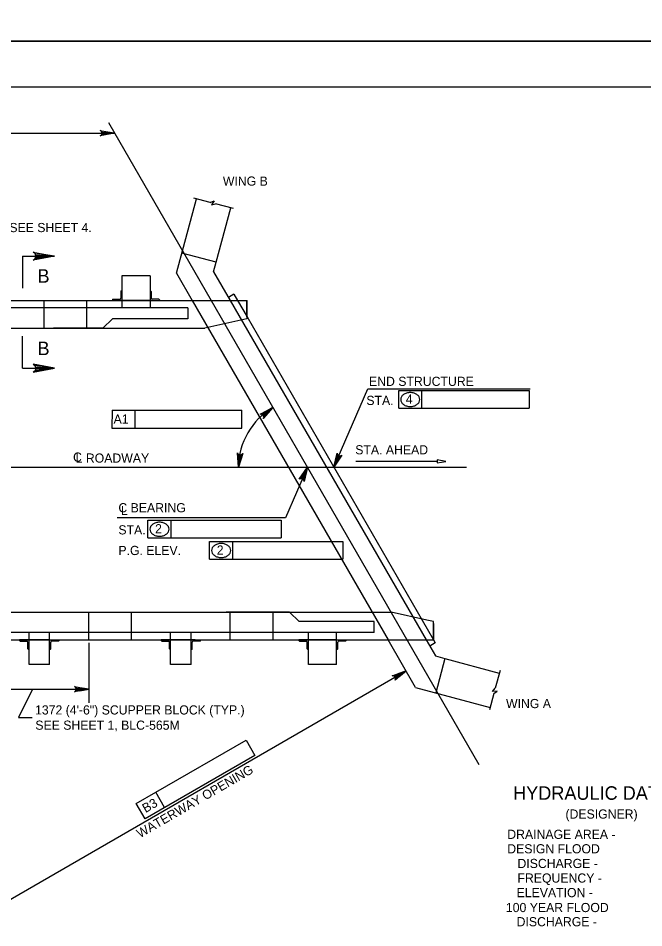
# Model space of a CAD drawing. Extents: x 638263 to 640360, y 293683 to 298655.
# Drawn here: x 638685.2 to 638890, y 296957.1 to 297255 of the extents above; entities that cross this region are included whole.
import ezdxf

# ---------------------------------------------------------------- set-up
doc = ezdxf.new("R2010")
doc.units = 0
for name, color, linetype in [('2', 7, 'Continuous'), ('3', 7, 'Continuous'), ('4', 7, 'Continuous'), ('PLT-BNDY', 7, 'Continuous')]:
    doc.layers.add(name, color=color, linetype=linetype)

msp = doc.modelspace()

# ---------------------------------------------------------------- linework, layer by layer
at = {"layer": '2'}
for p, q in [((638475.46, 297232.46), (639261.46, 297232.46)), ((638736.95, 297171.46), (638743.49, 297195.86)), ((638749.97, 297175.06), (638754.74, 297192.85)), ((638686.53, 297177.06), (638686.53, 297166.58)), ((638686.53, 297177.06), (638697.02, 297177.06)), ((638749.97, 297175.06), (638738.72, 297178.07)), ((638749.12, 297171.91), (638749.97, 297175.06)), ((638728.33, 297170.65), (638719.09, 297170.65)), ((638719.09, 297170.65), (638719.09, 297160.17)), ((638728.33, 297170.65), (638728.33, 297160.17)), ((638736.95, 297171.46), (638742.09, 297162.56)), ((638749.12, 297171.91), (638754.52, 297162.56)), ((638718.73, 297165.47), (638718.73, 297163.29)), ((638718.91, 297165.65), (638719.09, 297165.65)), ((638719.09, 297165.65), (638719.09, 297162.56)), ((638728.51, 297165.65), (638728.33, 297165.65)), ((638728.33, 297165.65), (638728.33, 297162.56)), ((638728.69, 297165.47), (638728.69, 297163.29)), ((638755.81, 297164.58), (638753.97, 297163.51)), ((638755.81, 297164.58), (638756.98, 297162.56)), ((638548.21, 297162.56), (638760.09, 297162.56)), ((638612.98, 297162.56), (638760.07, 297162.56)), ((638693.52, 297162.56), (638693.52, 297153.44)), ((638707.54, 297162.56), (638707.54, 297153.44)), ((638716, 297162.74), (638716, 297162.56)), ((638719.09, 297162.56), (638716, 297162.56)), ((638716.18, 297162.92), (638718.36, 297162.92)), ((638728.33, 297162.56), (638719.09, 297162.56)), ((638728.33, 297162.56), (638731.42, 297162.56)), ((638731.24, 297162.92), (638729.06, 297162.92)), ((638731.42, 297162.74), (638731.42, 297162.56)), ((638742.09, 297162.56), (638806.28, 297051.39)), ((638754.52, 297162.56), (638818.71, 297051.39)), ((638756.98, 297162.56), (638760.09, 297157.17)), ((638760.07, 297157.18), (638760.07, 297162.56)), ((638760.07, 297162.56), (638760.07, 297156.53)), ((638760.09, 297157.18), (638760.09, 297162.56)), ((638740.65, 297160.17), (638612.81, 297160.17)), ((638740.65, 297160.17), (638740.65, 297156.53)), ((638712.92, 297153.44), (638716.01, 297156.53)), ((638740.65, 297156.53), (638716.01, 297156.53)), ((638760.07, 297156.53), (638746.22, 297153.44)), ((638760.09, 297157.17), (638817.43, 297057.86)), ((638595.36, 297153.44), (638746.22, 297153.44)), ((638712.92, 297153.44), (638696.76, 297153.44)), ((638686.53, 297140.33), (638686.53, 297150.82)), ((638686.53, 297140.33), (638697.02, 297140.33)), ((638656.45, 297060.51), (638807.31, 297060.51)), ((638708.24, 297051.39), (638708.24, 297060.51)), ((638722.27, 297051.39), (638722.27, 297060.51)), ((638774.01, 297060.51), (638753.23, 297060.51)), ((638754.61, 297051.39), (638754.61, 297060.51)), ((638768.63, 297051.39), (638768.63, 297060.51)), ((638774.01, 297060.51), (638777.1, 297057.42)), ((638818.99, 297057.9), (638807.31, 297060.51)), ((638801.74, 297057.42), (638777.1, 297057.42)), ((638801.74, 297053.78), (638801.74, 297057.42)), ((638817.43, 297057.86), (638821.16, 297051.39)), ((638821.16, 297057.42), (638818.99, 297057.9)), ((638821.16, 297051.39), (638821.16, 297057.42)), ((638821.16, 297056.77), (638821.16, 297051.39)), ((638801.74, 297053.78), (638673.9, 297053.78)), ((638688.71, 297043.3), (638688.71, 297053.78)), ((638695.44, 297043.3), (638695.44, 297053.78)), ((638735.07, 297043.3), (638735.07, 297053.78)), ((638741.8, 297043.3), (638741.8, 297053.78)), ((638780.18, 297043.3), (638780.18, 297053.78)), ((638789.42, 297043.3), (638789.42, 297053.78)), ((638674.07, 297051.39), (638821.16, 297051.39)), ((638685.62, 297051.21), (638685.62, 297051.39)), ((638688.71, 297051.39), (638685.62, 297051.39)), ((638685.8, 297051.02), (638687.98, 297051.02)), ((638688.35, 297048.48), (638688.35, 297050.66)), ((638695.44, 297051.39), (638688.71, 297051.39)), ((638688.71, 297048.3), (638688.71, 297051.39)), ((638695.44, 297048.3), (638695.44, 297051.39)), ((638695.44, 297051.39), (638698.53, 297051.39)), ((638695.8, 297048.48), (638695.8, 297050.66)), ((638698.35, 297051.02), (638696.16, 297051.02)), ((638698.53, 297051.21), (638698.53, 297051.39)), ((638731.98, 297051.21), (638731.98, 297051.39)), ((638735.07, 297051.39), (638731.98, 297051.39)), ((638732.16, 297051.02), (638734.35, 297051.02)), ((638743.05, 297051.39), (638733.82, 297051.39)), ((638734.71, 297048.48), (638734.71, 297050.66)), ((638741.8, 297051.39), (638735.07, 297051.39)), ((638735.07, 297048.3), (638735.07, 297051.39)), ((638741.8, 297048.3), (638741.8, 297051.39)), ((638741.8, 297051.39), (638744.89, 297051.39)), ((638742.16, 297048.48), (638742.16, 297050.66)), ((638744.71, 297051.02), (638742.53, 297051.02)), ((638744.89, 297051.21), (638744.89, 297051.39)), ((638777.09, 297051.21), (638777.09, 297051.39)), ((638780.18, 297051.39), (638777.09, 297051.39)), ((638777.27, 297051.02), (638779.45, 297051.02)), ((638779.82, 297048.48), (638779.82, 297050.66)), ((638789.42, 297051.39), (638780.18, 297051.39)), ((638780.18, 297048.3), (638780.18, 297051.39)), ((638789.42, 297048.3), (638789.42, 297051.39)), ((638789.42, 297051.39), (638792.51, 297051.39)), ((638789.78, 297048.48), (638789.78, 297050.66)), ((638792.33, 297051.02), (638790.15, 297051.02)), ((638792.51, 297051.21), (638792.51, 297051.39)), ((638815.27, 297035.81), (638806.28, 297051.39)), ((638818.71, 297051.39), (638821.74, 297046.13)), ((638821.72, 297050.43), (638819.88, 297049.36)), ((638821.16, 297051.39), (638821.72, 297050.43)), ((638688.53, 297048.3), (638688.71, 297048.3)), ((638695.62, 297048.3), (638695.44, 297048.3)), ((638734.89, 297048.3), (638735.07, 297048.3)), ((638741.98, 297048.3), (638741.8, 297048.3)), ((638780, 297048.3), (638780.18, 297048.3)), ((638789.6, 297048.3), (638789.42, 297048.3)), ((638821.74, 297046.13), (638824.89, 297045.29)), ((638824.89, 297045.29), (638821.88, 297034.04)), ((638824.89, 297045.29), (638842.68, 297040.52)), ((638695.44, 297043.3), (638688.71, 297043.3)), ((638741.8, 297043.3), (638735.07, 297043.3)), ((638741.8, 297043.3), (638735.07, 297043.3)), ((638789.42, 297043.3), (638780.18, 297043.3)), ((638815.27, 297035.81), (638839.67, 297029.27))]:
    msp.add_line(p, q, dxfattribs=at)
for points in [[(638697.02, 297177.06), (638690.03, 297175.75), (638690.57, 297176.12), (638690.84, 297176.59), (638690.93, 297177.06), (638690.84, 297177.53), (638690.57, 297178), (638690.03, 297178.37), (638697.02, 297177.06), (638690.57, 297178), (638690.84, 297177.53), (638697.02, 297177.06), (638690.93, 297177.06), (638690.84, 297176.59), (638697.02, 297177.06), (638690.57, 297176.12)], [(638697.02, 297140.33), (638690.03, 297141.64), (638690.57, 297141.27), (638690.84, 297140.8), (638690.93, 297140.33), (638690.84, 297139.86), (638690.57, 297139.39), (638690.03, 297139.02), (638697.02, 297140.33), (638690.57, 297139.39), (638690.84, 297139.86), (638697.02, 297140.33), (638690.93, 297140.33), (638690.84, 297140.8), (638697.02, 297140.33), (638690.57, 297141.27)]]:
    msp.add_lwpolyline(points, dxfattribs=at)
for centre, radius, start, end in [((638718.91, 297165.47), 0.182, 90, 179.9984), ((638728.51, 297165.47), 0.182, 0.0016, 90), ((638716.18, 297162.74), 0.182, 90, 179.9984), ((638718.36, 297163.29), 0.364, 270, 359.9984), ((638729.06, 297163.29), 0.364, 180.0016, 270), ((638731.24, 297162.74), 0.182, 0.0016, 90), ((638685.8, 297051.21), 0.182, 180.0016, 270), ((638687.98, 297050.66), 0.364, 0.0016, 90), ((638696.16, 297050.66), 0.364, 90, 179.9984), ((638698.35, 297051.21), 0.182, 270, 359.9984), ((638732.16, 297051.21), 0.182, 180.0016, 270), ((638734.35, 297050.66), 0.364, 0.0016, 90), ((638742.53, 297050.66), 0.364, 90, 179.9984), ((638744.71, 297051.21), 0.182, 270, 359.9984), ((638777.27, 297051.21), 0.182, 180.0016, 270), ((638779.45, 297050.66), 0.364, 0.0016, 90), ((638790.15, 297050.66), 0.364, 90, 179.9984), ((638792.33, 297051.21), 0.182, 270, 359.9984), ((638688.53, 297048.48), 0.182, 180.0016, 270), ((638695.62, 297048.48), 0.182, 270, 359.9984), ((638734.89, 297048.48), 0.182, 180.0016, 270), ((638741.98, 297048.48), 0.182, 270, 359.9984), ((638780, 297048.48), 0.182, 180.0016, 270), ((638789.6, 297048.48), 0.182, 270, 359.9984)]:
    msp.add_arc(centre, radius, start, end, dxfattribs=at)
at = {"layer": '3'}
for p, q in [((638714.68, 297220.81), (638836.02, 297010.64)), ((638525.28, 297217.32), (638716.69, 297217.32)), ((638748.04, 297194.65), (638742.7, 297196.08)), ((638748.04, 297194.65), (638749.29, 297195.18)), ((638749.29, 297195.18), (638748.43, 297193.88)), ((638748.43, 297193.88), (638749.77, 297194.18)), ((638755.6, 297192.62), (638749.77, 297194.18)), ((638842.92, 297041.39), (638841.35, 297035.55)), ((638840.43, 297034.54), (638841.35, 297035.55)), ((638840.89, 297033.82), (638839.46, 297028.48)), ((638841.98, 297034.64), (638840.43, 297034.54)), ((638840.89, 297033.82), (638841.98, 297034.64))]:
    msp.add_line(p, q, dxfattribs=at)
at = {"layer": '4'}
for p, q in [((638788.52, 297107.93), (638799.64, 297133.65)), ((638799.64, 297133.65), (638852.83, 297133.65)), ((638809.74, 297133.03), (638817.32, 297133.03)), ((638809.74, 297127.26), (638809.74, 297133.03)), ((638817.32, 297127.26), (638817.32, 297133.03)), ((638817.32, 297133.03), (638852.5, 297133.03)), ((638852.5, 297133.03), (638852.5, 297127.26)), ((638715.88, 297126.66), (638715.87, 297120.75)), ((638715.88, 297126.66), (638723.44, 297126.66)), ((638723.43, 297120.75), (638723.44, 297126.66)), ((638723.44, 297126.66), (638758.4, 297126.66)), ((638758.39, 297120.75), (638758.4, 297126.66)), ((638809.74, 297127.26), (638852.5, 297127.26)), ((638715.87, 297120.75), (638758.39, 297120.75)), ((638546.93, 297107.93), (638831.95, 297107.93)), ((638779.85, 297107.93), (638772.67, 297091.32)), ((638822.3, 297109.86), (638795.66, 297109.86)), ((638772.67, 297091.32), (638717.6, 297091.32)), ((638727.65, 297090.56), (638735.22, 297090.56)), ((638727.65, 297084.79), (638727.65, 297090.56)), ((638735.22, 297084.79), (638735.22, 297090.56)), ((638735.22, 297090.56), (638771.23, 297090.56)), ((638771.23, 297090.56), (638771.23, 297084.79)), ((638727.65, 297084.79), (638771.23, 297084.79)), ((638747.84, 297077.82), (638747.84, 297083.59)), ((638747.84, 297083.59), (638755.41, 297083.59)), ((638755.41, 297077.82), (638755.41, 297083.59)), ((638755.41, 297083.59), (638791.42, 297083.59)), ((638791.42, 297083.59), (638791.42, 297077.82)), ((638747.84, 297077.82), (638791.42, 297077.82)), ((638708.24, 297050.46), (638708.24, 297030.82)), ((638677.89, 296963.76), (638812.12, 297041.26)), ((638675.9, 297035.25), (638708.24, 297035.25)), ((638689.86, 297035.25), (638685.27, 297026.02)), ((638685.27, 297026.02), (638689.7, 297026.02)), ((638730.22, 297001.51), (638759.8, 297018.55)), ((638759.8, 297018.55), (638762.67, 297013.56)), ((638762.67, 297013.56), (638726.69, 296992.83)), ((638723.81, 296997.83), (638730.22, 297001.51)), ((638733.1, 296996.52), (638730.22, 297001.51)), ((638726.69, 296992.83), (638723.81, 296997.83))]:
    msp.add_line(p, q, dxfattribs=at)
for points in [[(638716.69, 297217.32), (638712.03, 297216.45), (638712.39, 297216.69), (638712.57, 297217.01), (638712.63, 297217.32), (638712.57, 297217.63), (638712.39, 297217.94), (638712.03, 297218.19), (638716.69, 297217.32), (638712.39, 297217.94), (638712.57, 297217.63), (638716.69, 297217.32), (638712.63, 297217.32), (638712.57, 297217.01), (638716.69, 297217.32), (638712.39, 297216.69)], [(638768.58, 297127.44), (638765.41, 297123.92), (638765.54, 297124.34), (638765.5, 297124.7), (638765.35, 297124.98), (638765.12, 297125.19), (638764.78, 297125.33), (638764.35, 297125.31), (638768.58, 297127.44), (638764.78, 297125.33), (638765.12, 297125.19), (638768.58, 297127.44), (638765.35, 297124.98), (638765.5, 297124.7), (638768.58, 297127.44), (638765.54, 297124.34)], [(638757.31, 297107.91), (638757.01, 297112.64), (638757.22, 297112.26), (638757.5, 297112.04), (638757.81, 297111.94), (638758.12, 297111.96), (638758.46, 297112.11), (638758.75, 297112.43), (638757.31, 297107.91), (638758.46, 297112.11), (638758.12, 297111.96), (638757.31, 297107.91), (638757.81, 297111.94), (638757.5, 297112.04), (638757.31, 297107.91), (638757.22, 297112.26)], [(638788.52, 297107.93), (638789.57, 297112.55), (638789.65, 297112.12), (638789.87, 297111.83), (638790.13, 297111.66), (638790.44, 297111.58), (638790.8, 297111.63), (638791.17, 297111.86), (638788.52, 297107.93), (638790.8, 297111.63), (638790.44, 297111.58), (638788.52, 297107.93), (638790.13, 297111.66), (638789.87, 297111.83), (638788.52, 297107.93), (638789.65, 297112.12)], [(638779.85, 297107.93), (638778.8, 297103.3), (638778.71, 297103.73), (638778.5, 297104.02), (638778.24, 297104.2), (638777.93, 297104.27), (638777.57, 297104.23), (638777.2, 297104), (638779.85, 297107.93), (638777.57, 297104.23), (638777.93, 297104.27), (638779.85, 297107.93), (638778.24, 297104.2), (638778.5, 297104.02), (638779.85, 297107.93), (638778.71, 297103.73)], [(638812.13, 297041.26), (638808.53, 297038.17), (638808.71, 297038.56), (638808.72, 297038.93), (638808.61, 297039.22), (638808.4, 297039.47), (638808.09, 297039.65), (638807.65, 297039.68), (638812.13, 297041.26), (638808.09, 297039.65), (638808.4, 297039.47), (638812.13, 297041.26), (638808.61, 297039.22), (638808.72, 297038.93), (638812.13, 297041.26), (638808.71, 297038.56)], [(638708.24, 297035.25), (638703.58, 297034.38), (638703.94, 297034.62), (638704.13, 297034.94), (638704.18, 297035.25), (638704.13, 297035.56), (638703.94, 297035.87), (638703.58, 297036.12), (638708.24, 297035.25), (638703.94, 297035.87), (638704.13, 297035.56), (638708.24, 297035.25), (638704.18, 297035.25), (638704.13, 297034.94), (638708.24, 297035.25), (638703.94, 297034.62)]]:
    msp.add_lwpolyline(points, dxfattribs=at)
for points in [[(638789.24, 297110.83), (638790.15, 297110.44), (638788.52, 297107.93)], [(638822.3, 297110.34), (638822.3, 297109.38), (638825.18, 297109.86)], [(638779.13, 297105.02), (638778.23, 297105.41), (638779.85, 297107.93)], [(638809.28, 297040.19), (638809.78, 297039.32), (638812.13, 297041.26)], [(638705.29, 297035.74), (638705.29, 297034.76), (638708.24, 297035.25)]]:
    msp.add_lwpolyline(points, close=True, dxfattribs=at)
for centre, radius, start, end in [((638812.12, 297130.1), 1.71, 150.6308, 180), ((638812.79, 297129.72), 2.49, 126.3544, 150.6308), ((638813.24, 297129.12), 3.23, 106.9552, 126.3544), ((638813.52, 297128.17), 4.22, 90, 106.9552), ((638813.52, 297128.17), 4.22, 73.0448, 90), ((638813.81, 297129.12), 3.23, 53.6456, 73.0448), ((638814.25, 297129.72), 2.49, 29.3692, 53.6456), ((638814.93, 297130.1), 1.71, 0, 29.3692), ((638812.12, 297130.1), 1.71, 180, 209.3692), ((638812.79, 297130.48), 2.49, 209.3692, 233.6456), ((638813.24, 297131.08), 3.23, 233.6456, 253.0448), ((638813.52, 297132.03), 4.22, 253.0448, 270), ((638813.52, 297132.03), 4.22, 270, 286.9552), ((638813.81, 297131.08), 3.23, 286.9552, 306.3544), ((638814.25, 297130.48), 2.49, 306.3544, 330.6308), ((638814.93, 297130.1), 1.71, 330.6308, 0), ((638779.85, 297107.93), 22.54, 119.9992, 179.9979), ((638730.7, 297087.25), 2.49, 126.3544, 150.6308), ((638731.14, 297086.65), 3.23, 106.9552, 126.3544), ((638731.43, 297085.7), 4.22, 90, 106.9552), ((638731.43, 297085.7), 4.22, 73.0448, 90), ((638731.72, 297086.65), 3.23, 53.6456, 73.0448), ((638732.16, 297087.25), 2.49, 29.3692, 53.6456), ((638730.02, 297087.63), 1.71, 150.6308, 180), ((638730.02, 297087.63), 1.71, 180, 209.3692), ((638730.7, 297088.01), 2.49, 209.3692, 233.6456), ((638732.16, 297088.01), 2.49, 306.3544, 330.6308), ((638732.84, 297087.63), 1.71, 0, 29.3692), ((638732.84, 297087.63), 1.71, 330.6308, 0), ((638731.14, 297088.61), 3.23, 233.6456, 253.0448), ((638731.43, 297089.56), 4.22, 253.0448, 270), ((638731.43, 297089.56), 4.22, 270, 286.9552), ((638731.72, 297088.61), 3.23, 286.9552, 306.3544), ((638750.21, 297080.66), 1.71, 150.6308, 180), ((638750.21, 297080.66), 1.71, 180, 209.3692), ((638750.89, 297080.28), 2.49, 126.3544, 150.6308), ((638751.33, 297079.68), 3.23, 106.9552, 126.3544), ((638751.62, 297078.74), 4.22, 90, 106.9552), ((638751.62, 297078.74), 4.22, 73.0448, 90), ((638751.91, 297079.68), 3.23, 53.6456, 73.0448), ((638752.35, 297080.28), 2.49, 29.3692, 53.6456), ((638753.03, 297080.66), 1.71, 0, 29.3692), ((638753.03, 297080.66), 1.71, 330.6308, 0), ((638750.89, 297081.04), 2.49, 209.3692, 233.6456), ((638751.33, 297081.64), 3.23, 233.6456, 253.0448), ((638751.62, 297082.59), 4.22, 253.0448, 270), ((638751.62, 297082.59), 4.22, 270, 286.9552), ((638751.91, 297081.64), 3.23, 286.9552, 306.3544), ((638752.35, 297081.04), 2.49, 306.3544, 330.6308)]:
    msp.add_arc(centre, radius, start, end, dxfattribs=at)
at = {"layer": 'PLT-BNDY'}
for points in [[(638435.46, 297841.46), (639276.46, 297841.46), (639276.46, 297247.46), (638435.46, 297247.46)], [(638435.46, 297247.46), (639276.46, 297247.46), (639276.46, 296653.46), (638435.46, 296653.46)]]:
    msp.add_lwpolyline(points, close=True, dxfattribs=at)

# ---------------------------------------------------------------- texts
at = {"layer": '4'}
for s, height, p in [('WING B', 3, (638752.17, 297200.12)), ('FOR VIEW B-B SEE SHEET 4.', 3, (638653.52, 297184.91)), ('B', 4.43, (638691.48, 297144.63)), ('END STRUCTURE', 3, (638800.02, 297134.55)), ('STA.', 3, (638799.15, 297128.31)), ('4', 3, (638812.07, 297128.75)), ('STA. AHEAD', 3, (638795.51, 297112.14)), ('C', 3, (638703.12, 297109.75)), ('L ROADWAY', 3, (638703.97, 297109.43)), ('C BEARING', 3, (638717.97, 297093.17)), ('L', 3, (638718.8, 297092.25)), ('2', 3, (638729.98, 297086.28)), ('STA.', 3, (638717.97, 297085.93)), ('P.G. ELEV.', 3, (638717.97, 297079.18)), ('2', 3, (638750.17, 297079.31)), ('1372 (4\'-6") SCUPPER BLOCK (TYP.)', 3, (638690.68, 297026.97)), ('WING A', 3, (638844.88, 297029.06)), ('SEE SHEET 1, BLC-565M', 3, (638690.78, 297021.98)), ('HYDRAULIC DATA', 4.4292, (638847.2, 296999.04)), ('(DESIGNER)', 3, (638864.34, 296992.88)), ('DRAINAGE AREA - ', 3, (638845.28, 296986.24)), ('DESIGN FLOOD  ', 3, (638845.28, 296981.5)), ('   DISCHARGE - ', 3, (638845.28, 296976.7)), ('   FREQUENCY - ', 3, (638845.28, 296971.93)), ('   ELEVATION - ', 3, (638845, 296967.16)), ('100 YEAR FLOOD', 3, (638844.83, 296962.27)), ('   DISCHARGE - ', 3, (638845, 296957.63))]:
    msp.add_text(s, height=height, dxfattribs=at).set_placement(p)
for s, height, rotation, p in [('B', 4.43, 360, (638691.48, 297168.34)), ('A1', 3, 359.9382, (638716.39, 297122.21)), ('WATERWAY OPENING', 3, 30, (638725.02, 296986.43)), ('B3', 3, 29.9438, (638726.86, 296994.68))]:
    msp.add_text(s, height=height, rotation=rotation, dxfattribs=at).set_placement(p)

doc.saveas('drawing.dxf')
